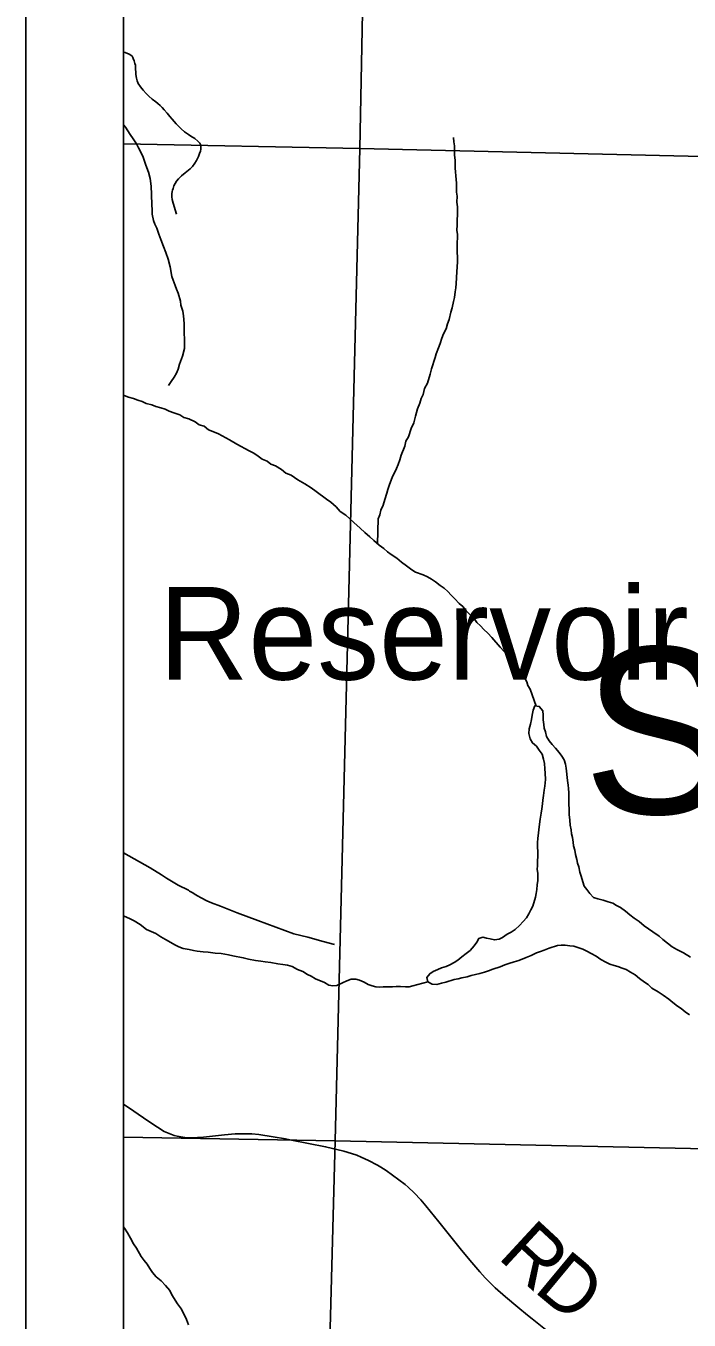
# Model space of a CAD drawing. Extents: x -7.9 to 76.1, y 0 to 22.
# Drawn here: x 2 to 2.678, y 15.245 to 16.568 of the extents above; entities that cross this region are included whole.
import ezdxf

# ---------------------------------------------------------------- set-up
doc = ezdxf.new("R2010")
doc.units = 0
for name, color, linetype in [('GM_X_County_Road', 7, 'Continuous'), ('GM_X_County_Road_Text', 7, 'Continuous'), ('GM_X_Major_Lake', 7, 'Continuous'), ('GM_X_Major_Lake_Text', 7, 'Continuous'), ('GM_X_Minor_River', 7, 'Continuous'), ('GM_X_Section', 7, 'Continuous'), ('GM_X_Township_Road', 7, 'Continuous'), ('GM_X_Township_Text', 7, 'Continuous'), ('SC_Scratch1', 7, 'Continuous'), ('SH_Data', 7, 'Continuous')]:
    doc.layers.add(name, color=color, linetype=linetype)

msp = doc.modelspace()

# ---------------------------------------------------------------- linework, layer by layer
at = {"layer": 'GM_X_County_Road'}
msp.add_lwpolyline([(2.1, 15.4661), (2.1, 15.4661), (2.1103, 15.459), (2.1246, 15.4491), (2.1347, 15.4424), (2.1416, 15.4383), (2.1447, 15.4369), (2.1483, 15.4355), (2.1516, 15.4342), (2.1549, 15.4334), (2.1604, 15.4323), (2.1651, 15.4318), (2.17, 15.4317), (2.1755, 15.4319), (2.1817, 15.4324), (2.2032, 15.4349), (2.2142, 15.4357), (2.2195, 15.4358), (2.2312, 15.4356), (2.2382, 15.435), (2.2528, 15.4328), (2.2656, 15.4305), (2.2718, 15.4294), (2.3065, 15.4225), (2.3252, 15.4181), (2.3331, 15.4157), (2.3385, 15.4138), (2.3429, 15.412), (2.3504, 15.4086), (2.3595, 15.4038), (2.3632, 15.4016), (2.3685, 15.3982), (2.3815, 15.3889), (2.3879, 15.3839), (2.391, 15.3812), (2.3971, 15.3756), (2.4038, 15.3684), (2.4091, 15.3622), (2.4224, 15.3459), (2.4457, 15.3169), (2.4561, 15.3042), (2.4644, 15.2946), (2.4699, 15.2887), (2.4762, 15.2822), (2.48, 15.2785), (2.4904, 15.2693), (2.503, 15.2585), (2.5131, 15.2504), (2.5179, 15.2466), (2.5313, 15.2357)], dxfattribs=at)
at = {"layer": 'GM_X_Major_Lake'}
for points in [[(2.6798, 15.6162), (2.6726, 15.6207), (2.6657, 15.624), (2.6611, 15.6269), (2.6515, 15.6343), (2.6477, 15.6377), (2.6411, 15.6421), (2.6369, 15.6454), (2.6323, 15.6484), (2.6273, 15.6529), (2.622, 15.6562), (2.6178, 15.6595), (2.6132, 15.6632), (2.6082, 15.6669), (2.604, 15.6691), (2.6002, 15.6713), (2.5956, 15.6728), (2.5903, 15.6746), (2.5849, 15.676), (2.5804, 15.6774), (2.5769, 15.6815), (2.5738, 15.6853), (2.5711, 15.689), (2.5695, 15.6932), (2.5679, 15.6992), (2.5667, 15.7033), (2.5654, 15.7086), (2.5642, 15.7124), (2.5634, 15.7162), (2.5622, 15.7211), (2.5614, 15.7256), (2.5602, 15.7301), (2.5597, 15.7339), (2.5589, 15.7385), (2.558, 15.7422), (2.5576, 15.7464), (2.5568, 15.7513), (2.5563, 15.7562), (2.5558, 15.7619), (2.5557, 15.7672), (2.5552, 15.7729), (2.5552, 15.7775), (2.5554, 15.7843), (2.555, 15.7885), (2.5545, 15.7922), (2.5541, 15.7968), (2.5527, 15.8093), (2.5519, 15.8134), (2.5507, 15.818), (2.5483, 15.8217), (2.5456, 15.8254), (2.5418, 15.8299), (2.5383, 15.8337), (2.5352, 15.8374), (2.5325, 15.8419), (2.5313, 15.8464), (2.5301, 15.8502), (2.5296, 15.854), (2.5291, 15.8589), (2.5291, 15.8635), (2.5286, 15.868), (2.5251, 15.8725), (2.5206, 15.8732), (2.5188, 15.8686), (2.5177, 15.8636), (2.517, 15.8591), (2.516, 15.8545), (2.5149, 15.8495), (2.5143, 15.845), (2.5159, 15.8393), (2.5182, 15.8352), (2.5221, 15.8319), (2.5251, 15.8277), (2.5279, 15.8236)], [(2.5279, 15.8236), (2.5295, 15.8187), (2.5303, 15.8142), (2.5308, 15.8089), (2.5312, 15.8043), (2.5313, 15.7979), (2.5307, 15.7911), (2.53, 15.7869), (2.5294, 15.7815), (2.5287, 15.7766), (2.5284, 15.7728), (2.5277, 15.7679), (2.527, 15.7633), (2.526, 15.7572), (2.525, 15.7496), (2.5244, 15.7432), (2.5237, 15.7375), (2.5234, 15.7333), (2.5236, 15.7196), (2.5233, 15.7143), (2.5234, 15.7098), (2.5231, 15.706), (2.5236, 15.7022), (2.5237, 15.6946), (2.523, 15.6901), (2.5227, 15.6855), (2.522, 15.6813), (2.5213, 15.6775), (2.5185, 15.6684), (2.5163, 15.6645), (2.5144, 15.6607), (2.5119, 15.6565), (2.5085, 15.6526), (2.5048, 15.6488), (2.5003, 15.6445), (2.4962, 15.6418), (2.4921, 15.6398), (2.4876, 15.6363), (2.4839, 15.6348), (2.4793, 15.6339), (2.4748, 15.635), (2.471, 15.6357), (2.4672, 15.6367), (2.4634, 15.6355), (2.4612, 15.6317), (2.4586, 15.6279), (2.4545, 15.6232), (2.4504, 15.6201), (2.446, 15.6166), (2.4419, 15.6132), (2.4381, 15.6108), (2.4336, 15.6085), (2.4299, 15.6069), (2.425, 15.6053), (2.4212, 15.6037), (2.4167, 15.6017), (2.413, 15.5994), (2.41, 15.5955), (2.4112, 15.591), (2.4154, 15.5888), (2.4203, 15.5885), (2.4252, 15.5897), (2.4294, 15.5906), (2.438, 15.5934), (2.4422, 15.5942), (2.446, 15.595), (2.4512, 15.5963), (2.4554, 15.5975), (2.4599, 15.5987), (2.4644, 15.5995), (2.4689, 15.6011), (2.4731, 15.6023), (2.4776, 15.6039), (2.4851, 15.6064), (2.49, 15.6083), (2.4941, 15.6099), (2.4994, 15.6115), (2.5043, 15.6128), (2.5118, 15.6159), (2.5167, 15.6179), (2.5223, 15.6207), (2.5265, 15.6222), (2.5302, 15.6235), (2.5351, 15.6254), (2.5438, 15.6282), (2.5475, 15.6287), (2.5517, 15.6284), (2.5563, 15.6277), (2.5604, 15.6274), (2.5646, 15.6263), (2.5696, 15.6245), (2.5738, 15.6223), (2.5783, 15.6201), (2.5833, 15.6172), (2.5879, 15.6139), (2.5932, 15.6113), (2.5971, 15.6091), (2.6016, 15.6077), (2.6054, 15.6066), (2.61, 15.6052), (2.6138, 15.6037)], [(2.6138, 15.6037), (2.6184, 15.6011), (2.623, 15.5982), (2.6276, 15.5945), (2.6326, 15.5908), (2.6364, 15.5882), (2.6403, 15.5845), (2.6468, 15.5808), (2.6517, 15.5775), (2.6575, 15.5734), (2.6617, 15.57), (2.6663, 15.5663), (2.6701, 15.5637), (2.6744, 15.5604), (2.6786, 15.5575)]]:
    msp.add_lwpolyline(points, dxfattribs=at)
at = {"layer": 'GM_X_Minor_River'}
for points in [[(2.1, 16.4669), (2.1019, 16.4646), (2.1066, 16.4571), (2.1097, 16.4526), (2.1132, 16.4473), (2.1152, 16.4432), (2.1195, 16.4349), (2.1211, 16.4308), (2.1227, 16.4255), (2.1254, 16.4183), (2.1271, 16.4119), (2.128, 16.404), (2.1285, 16.3956), (2.1287, 16.385), (2.1291, 16.3801), (2.1292, 16.3755), (2.1305, 16.3691), (2.132, 16.3654), (2.134, 16.3612), (2.136, 16.3552), (2.138, 16.3495), (2.1408, 16.3424), (2.1432, 16.3363), (2.1455, 16.3296), (2.1476, 16.3216), (2.1493, 16.3118), (2.1508, 16.308), (2.1528, 16.3028), (2.154, 16.299), (2.1556, 16.2948), (2.158, 16.2865), (2.1585, 16.2824), (2.1605, 16.2763), (2.1613, 16.2718), (2.1614, 16.268), (2.1618, 16.2635), (2.1623, 16.2381), (2.1601, 16.2304), (2.1573, 16.2221), (2.1558, 16.2171), (2.154, 16.2129), (2.1518, 16.2091), (2.1485, 16.2045), (2.1459, 16.2006)], [(2.4374, 16.4538), (2.4378, 16.4493), (2.4383, 16.4455), (2.4385, 16.436), (2.4389, 16.4304), (2.4391, 16.4224), (2.44, 16.411), (2.4405, 16.4072), (2.4406, 16.3981), (2.4411, 16.394), (2.4408, 16.3879), (2.4413, 16.383), (2.4414, 16.375), (2.4411, 16.3697), (2.4412, 16.3644), (2.4409, 16.3591), (2.4414, 16.3549), (2.4415, 16.3511), (2.4411, 16.3469), (2.4412, 16.3432), (2.441, 16.3363), (2.4414, 16.3318), (2.4415, 16.3272), (2.4412, 16.3215), (2.4409, 16.317), (2.4403, 16.3105), (2.44, 16.3048), (2.4397, 16.3003), (2.439, 16.2961), (2.4384, 16.2904), (2.4373, 16.2862), (2.4359, 16.2797), (2.4348, 16.2755), (2.4331, 16.2679), (2.4313, 16.2633), (2.4298, 16.2584), (2.4273, 16.2534), (2.4255, 16.2488), (2.4237, 16.2435), (2.4219, 16.2389), (2.4197, 16.2328), (2.4186, 16.229), (2.415, 16.2175), (2.4136, 16.2122), (2.4107, 16.203), (2.4078, 16.1973), (2.4064, 16.1912), (2.4042, 16.187), (2.4028, 16.1824), (2.4006, 16.1767), (2.3985, 16.1691), (2.3967, 16.1622), (2.3942, 16.1565), (2.3913, 16.1481), (2.3887, 16.1435), (2.3877, 16.1385), (2.384, 16.1294), (2.3826, 16.1244), (2.3808, 16.1198), (2.379, 16.1156), (2.3746, 16.1064), (2.3728, 16.1019), (2.3717, 16.0981), (2.3703, 16.0942), (2.3692, 16.0904), (2.367, 16.0839), (2.3653, 16.0782), (2.3631, 16.0729), (2.362, 16.0683), (2.3602, 16.0641), (2.3597, 16.0388)], [(2.1, 16.1905), (2.1007, 16.1903), (2.1049, 16.1885), (2.1102, 16.1871)], [(2.1102, 16.1871), (2.1144, 16.1853), (2.119, 16.1842), (2.1232, 16.182), (2.1289, 16.1806), (2.133, 16.1791), (2.138, 16.1777), (2.1426, 16.1763), (2.1464, 16.1741), (2.1513, 16.1726), (2.1574, 16.1705), (2.1616, 16.1679), (2.1666, 16.1665), (2.1731, 16.1632), (2.1773, 16.1602), (2.1822, 16.1588), (2.1868, 16.1551), (2.1929, 16.1529), (2.1971, 16.1511), (2.2009, 16.1489), (2.2082, 16.1448), (2.2158, 16.1404), (2.2284, 16.1338), (2.233, 16.1312), (2.2376, 16.1283), (2.2418, 16.1253), (2.2468, 16.1231), (2.2506, 16.1202), (2.2552, 16.1184), (2.2613, 16.1147), (2.2659, 16.111), (2.2713, 16.1088), (2.2781, 16.104), (2.2854, 16.0999), (2.2919, 16.0959), (2.2969, 16.0922), (2.3076, 16.0844), (2.3118, 16.0814), (2.3172, 16.0766), (2.3215, 16.0717), (2.3272, 16.0681), (2.3314, 16.0643), (2.3353, 16.0606), (2.3418, 16.0547), (2.3468, 16.0502), (2.3518, 16.0457), (2.356, 16.042), (2.3614, 16.0372), (2.366, 16.0339), (2.3699, 16.0305), (2.3737, 16.0279), (2.3794, 16.0239), (2.3841, 16.0198), (2.3894, 16.0161), (2.3948, 16.012), (2.3986, 16.0098), (2.4062, 16.0069), (2.4108, 16.0051), (2.415, 16.0025), (2.4188, 15.9999), (2.4238, 15.9962), (2.4277, 15.9932), (2.4315, 15.9899), (2.435, 15.9862), (2.4388, 15.9824), (2.4431, 15.9776), (2.4469, 15.9746), (2.4504, 15.9701), (2.4539, 15.9664), (2.4581, 15.9627), (2.4612, 15.9582), (2.465, 15.9548), (2.4685, 15.9511), (2.4724, 15.9474), (2.4766, 15.9429), (2.4851, 15.9332), (2.4893, 15.9287), (2.4943, 15.9231), (2.4978, 15.9183), (2.5017, 15.9142), (2.5048, 15.91), (2.5079, 15.9055), (2.5102, 15.9014), (2.5122, 15.8977), (2.5134, 15.8939), (2.5157, 15.8901), (2.522, 15.8729)], [(2.1, 15.6584), (2.1005, 15.6583), (2.1059, 15.6557), (2.1108, 15.6535), (2.1169, 15.6498), (2.1235, 15.6447), (2.133, 15.6403), (2.138, 15.637), (2.1429, 15.6344), (2.1483, 15.6314), (2.1525, 15.6289), (2.1563, 15.627), (2.1609, 15.6252), (2.1669, 15.6242), (2.1715, 15.6231), (2.1753, 15.6225), (2.1814, 15.6218), (2.1863, 15.6215), (2.1935, 15.6205), (2.1999, 15.6199), (2.2072, 15.6188), (2.2117, 15.6178), (2.2223, 15.6157), (2.2277, 15.6143), (2.2349, 15.6129), (2.2402, 15.6122), (2.2447, 15.6116), (2.2504, 15.6109), (2.2576, 15.6095), (2.2629, 15.6088), (2.2675, 15.6082), (2.2724, 15.6067), (2.2778, 15.6038), (2.2831, 15.6016), (2.2881, 15.5987), (2.2919, 15.5968), (2.2961, 15.5943), (2.3053, 15.5903), (2.3099, 15.5877), (2.314, 15.587), (2.3182, 15.5875), (2.3238, 15.5902), (2.3283, 15.5922), (2.3328, 15.5938), (2.3374, 15.5939), (2.3412, 15.5928), (2.3461, 15.5906), (2.35, 15.5884), (2.3541, 15.587), (2.3579, 15.5859), (2.3617, 15.5856), (2.3655, 15.586), (2.3708, 15.5861), (2.375, 15.5858), (2.3788, 15.5863), (2.3833, 15.5863), (2.3882, 15.5861), (2.392, 15.5861), (2.3958, 15.5869), (2.4112, 15.591)], [(2.1, 15.3408), (2.1008, 15.3394), (2.1039, 15.3345), (2.107, 15.3293), (2.1101, 15.3233), (2.1132, 15.3188), (2.1179, 15.3105), (2.121, 15.3064), (2.1241, 15.3027), (2.1268, 15.2982), (2.1296, 15.294), (2.1334, 15.2896), (2.1384, 15.2855), (2.1427, 15.2806), (2.1473, 15.2758), (2.1493, 15.2713), (2.1551, 15.2619), (2.1593, 15.2567), (2.1644, 15.2461), (2.1664, 15.2405)]]:
    msp.add_lwpolyline(points, dxfattribs=at)
at = {"layer": 'GM_X_Section'}
for points in [[(2.3613, 17.4511), (3.3681, 17.4339), (3.3491, 16.4191), (2.3414, 16.4427)], [(3.3491, 16.4191), (3.3274, 15.4069), (2.3164, 15.4286), (2.3414, 16.4427)], [(2.3164, 15.4286), (3.3274, 15.4069), (3.3054, 14.3948), (2.2894, 14.4198)]]:
    msp.add_lwpolyline(points, close=True, dxfattribs=at)
at = {"layer": 'GM_X_Township_Road'}
for points in [[(2.1539, 16.3754), (2.1508, 16.3867), (2.1498, 16.3904), (2.1494, 16.3931), (2.1493, 16.3962), (2.1496, 16.3987), (2.15, 16.4002), (2.1505, 16.4017), (2.1515, 16.4044), (2.1526, 16.4069), (2.154, 16.4092), (2.1562, 16.4117), (2.1591, 16.4146), (2.1628, 16.4178), (2.1679, 16.422), (2.1703, 16.4243), (2.1729, 16.4278), (2.1746, 16.4305), (2.1766, 16.4344), (2.1777, 16.4374), (2.1786, 16.4398), (2.179, 16.4421), (2.1789, 16.4449), (2.1785, 16.4466), (2.1778, 16.4481), (2.176, 16.4503), (2.1727, 16.4529), (2.1687, 16.4554), (2.1662, 16.4571), (2.1624, 16.4598), (2.1588, 16.4627), (2.1536, 16.468), (2.1495, 16.4725), (2.1471, 16.4752), (2.1444, 16.4788), (2.1415, 16.4822), (2.1395, 16.4844), (2.1373, 16.4865), (2.1351, 16.4885), (2.1328, 16.4904), (2.1292, 16.4932), (2.1259, 16.496), (2.1229, 16.499), (2.1201, 16.5022), (2.1174, 16.5055), (2.115, 16.5091), (2.1138, 16.5118), (2.113, 16.5145), (2.1124, 16.5182), (2.1122, 16.5261), (2.112, 16.5279), (2.1116, 16.5296), (2.1108, 16.5322), (2.1098, 16.5347), (2.1094, 16.5356), (2.1086, 16.5369), (2.1074, 16.5381), (2.1058, 16.5389), (2.1014, 16.5407), (2.1, 16.5412)], [(2.1, 15.7228), (2.1271, 15.7075), (2.1386, 15.7005), (2.1437, 15.697), (2.1438, 15.6969), (2.1556, 15.6899), (2.1663, 15.6846), (2.1675, 15.6838), (2.1708, 15.682), (2.1723, 15.6811), (2.1755, 15.679), (2.1793, 15.6768), (2.185, 15.6739), (2.1899, 15.6718), (2.1992, 15.6685), (2.216, 15.6617), (2.2371, 15.6536), (2.2742, 15.6402), (2.2883, 15.6368), (2.3039, 15.6322), (2.3157, 15.6291)]]:
    msp.add_lwpolyline(points, dxfattribs=at)
at = {"layer": 'SC_Scratch1'}
for points in [[(2.1, 17.4553), (2.1, 16.4475), (2.3414, 16.4427), (2.3613, 17.4511)], [(2.1, 16.4475), (2.1, 15.4325), (2.3164, 15.4286), (2.3414, 16.4427)], [(2.1, 15.4325), (2.1, 14.424), (2.2894, 14.4198), (2.3164, 15.4286)]]:
    msp.add_lwpolyline(points, close=True, dxfattribs=at)
at = {"layer": 'SH_Data'}
for p, q in [((2, 21), (2, 14)), ((2.1, 20.9), (2.1, 14.1))]:
    msp.add_line(p, q, dxfattribs=at)

# ---------------------------------------------------------------- texts
at = {"layer": 'GM_X_County_Road_Text'}
for s, rotation, p in [('R', 317.2388, (2.4815, 15.3094)), ('D', 320.3013, (2.5182, 15.2755))]:
    msp.add_text(s, height=0.0568, rotation=rotation, dxfattribs=at).set_placement(p)
at = {"layer": 'GM_X_Major_Lake_Text'}
msp.add_text('Reservoir', height=0.09469, rotation=0.0045, dxfattribs=at).set_placement((2.1361, 15.8999))
at = {"layer": 'GM_X_Township_Text'}
msp.add_text('SOMERSET', height=0.17, rotation=0, dxfattribs=at).set_placement((2.5697, 15.7629))

doc.saveas('drawing.dxf')
